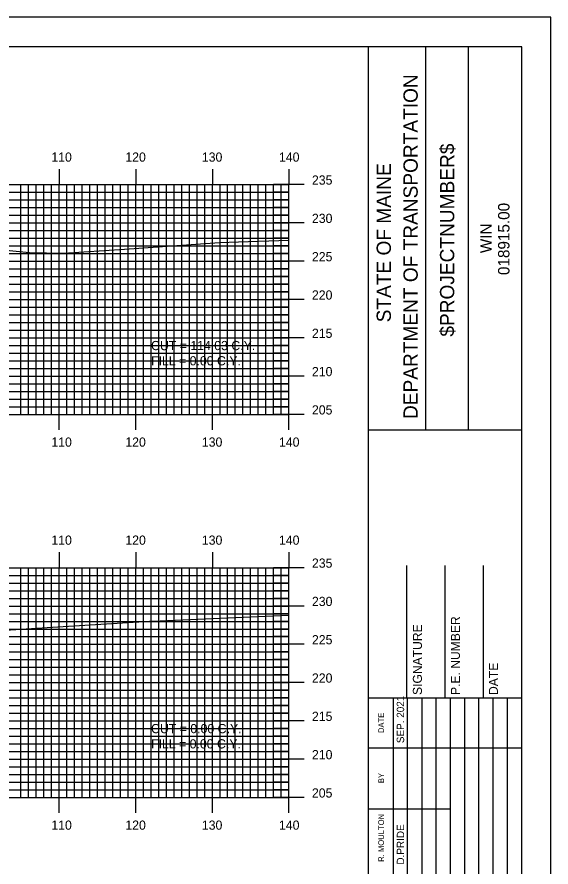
# Model space of a CAD drawing. Extents: x 850955 to 851298, y 364785 to 365005.
# Drawn here: x 851225.2 to 851294.9, y 364894.2 to 365005.1 of the extents above; entities that cross this region are included whole.
import ezdxf

# ---------------------------------------------------------------- set-up
doc = ezdxf.new("R2010")
doc.units = 0
for name, color, linetype in [('BORDER', 7, 'Continuous'), ('D_Text_Standard', 7, 'Continuous'), ('H_V ANNOTATION', 7, 'Continuous'), ('MAJOR', 7, 'Continuous'), ('MINOR', 7, 'Continuous'), ('PLOT BOUNDARY', 7, 'Continuous'), ('S_Roadway_Centerline', 7, 'Continuous')]:
    doc.layers.add(name, color=color, linetype=linetype)

msp = doc.modelspace()

# ---------------------------------------------------------------- linework, layer by layer
at = {"layer": 'BORDER'}
for p, q in [((851271.08, 364791.23), (851271.08, 365001.23)), ((851278.54, 364951.23), (851278.54, 365001.23)), ((851284.13, 364951.23), (851284.13, 365001.23)), ((851271.08, 364951.22), (851291.08, 364951.22)), ((851276.08, 364916.24), (851276.08, 364933.53)), ((851281.08, 364916.24), (851281.08, 364933.53)), ((851286.08, 364916.24), (851286.08, 364933.53)), ((851271.08, 364916.24), (851291.08, 364916.24))]:
    msp.add_line(p, q, dxfattribs=at)
msp.add_lwpolyline([(850971.08, 364791.23), (851291.08, 364791.23), (851291.08, 365001.23), (850971.08, 365001.23)], close=True, dxfattribs=at)
for points in [[(851274.31, 364909.74), (851274.31, 364916.24)], [(851276.17, 364881.24), (851276.17, 364916.24)], [(851278.04, 364916.24), (851278.04, 364881.24)], [(851279.9, 364881.24), (851279.9, 364916.24)], [(851281.76, 364881.24), (851281.76, 364916.24)], [(851283.63, 364881.24), (851283.63, 364916.24)], [(851285.49, 364881.24), (851285.49, 364916.24)], [(851287.35, 364881.24), (851287.35, 364916.24)], [(851289.22, 364881.24), (851289.22, 364916.24)], [(851274.31, 364881.24), (851274.31, 364914.83)], [(851271.08, 364909.74), (851291.08, 364909.74)], [(851271.08, 364901.74), (851274.31, 364901.74)], [(851274.31, 364901.74), (851281.76, 364901.74)]]:
    msp.add_lwpolyline(points, dxfattribs=at)
at = {"layer": 'MAJOR'}
for p, q in [((851230.68, 364985.24), (851230.68, 364983.23)), ((851240.68, 364985.24), (851240.68, 364983.23)), ((851250.68, 364985.24), (851250.68, 364983.23)), ((851260.68, 364985.24), (851260.68, 364983.23)), ((850980.68, 364983.23), (851260.68, 364983.23)), ((850980.68, 364983.23), (851260.68, 364983.23)), ((851230.68, 364953.23), (851230.68, 364983.23)), ((851240.68, 364953.23), (851240.68, 364983.23)), ((851250.68, 364953.23), (851250.68, 364983.23)), ((851262.68, 364983.23), (851258.67, 364983.23)), ((851260.68, 364953.23), (851260.68, 364983.23)), ((851260.68, 364953.23), (851260.68, 364983.23)), ((850980.68, 364978.23), (851260.68, 364978.23)), ((851262.68, 364978.23), (851258.67, 364978.23)), ((850980.68, 364973.23), (851260.68, 364973.23)), ((851262.68, 364973.23), (851258.67, 364973.23)), ((850980.68, 364968.23), (851260.68, 364968.23)), ((851262.68, 364968.23), (851258.67, 364968.23)), ((850980.68, 364963.23), (851260.68, 364963.23)), ((851262.68, 364963.23), (851258.67, 364963.23)), ((850980.68, 364958.23), (851260.68, 364958.23)), ((851262.68, 364958.23), (851258.67, 364958.23)), ((850980.68, 364953.23), (851260.68, 364953.23)), ((850980.68, 364953.23), (851260.68, 364953.23)), ((851230.68, 364951.23), (851230.68, 364953.23)), ((851240.68, 364951.23), (851240.68, 364953.23)), ((851250.68, 364951.23), (851250.68, 364953.23)), ((851262.68, 364953.23), (851258.67, 364953.23)), ((851260.68, 364951.23), (851260.68, 364953.23)), ((851230.68, 364935.24), (851230.68, 364933.23)), ((851240.68, 364935.24), (851240.68, 364933.23)), ((851250.68, 364935.24), (851250.68, 364933.23)), ((851260.68, 364935.24), (851260.68, 364933.23)), ((850980.68, 364933.23), (851260.68, 364933.23)), ((850980.68, 364933.23), (851260.68, 364933.23)), ((851230.68, 364903.23), (851230.68, 364933.23)), ((851240.68, 364903.23), (851240.68, 364933.23)), ((851250.68, 364903.23), (851250.68, 364933.23)), ((851262.68, 364933.23), (851258.67, 364933.23)), ((851260.68, 364903.23), (851260.68, 364933.23)), ((851260.68, 364903.23), (851260.68, 364933.23)), ((850980.68, 364928.23), (851260.68, 364928.23)), ((851262.68, 364928.23), (851258.67, 364928.23)), ((850980.68, 364923.23), (851260.68, 364923.23)), ((851262.68, 364923.23), (851258.67, 364923.23)), ((850980.68, 364918.23), (851260.68, 364918.23)), ((851262.68, 364918.23), (851258.67, 364918.23)), ((850980.68, 364913.23), (851260.68, 364913.23)), ((851262.68, 364913.23), (851258.67, 364913.23)), ((850980.68, 364908.23), (851260.68, 364908.23)), ((851262.68, 364908.23), (851258.67, 364908.23)), ((850980.68, 364903.23), (851260.68, 364903.23)), ((850980.68, 364903.23), (851260.68, 364903.23)), ((851230.68, 364901.23), (851230.68, 364903.23)), ((851240.68, 364901.23), (851240.68, 364903.23)), ((851250.68, 364901.23), (851250.68, 364903.23)), ((851262.68, 364903.23), (851258.67, 364903.23)), ((851260.68, 364901.23), (851260.68, 364903.23))]:
    msp.add_line(p, q, dxfattribs=at)
at = {"layer": 'MINOR'}
for p, q in [((851225.68, 364953.23), (851225.68, 364983.23)), ((851226.68, 364953.23), (851226.68, 364983.23)), ((851227.68, 364953.23), (851227.68, 364983.23)), ((851228.68, 364953.23), (851228.68, 364983.23)), ((851229.68, 364953.23), (851229.68, 364983.23)), ((851231.68, 364953.23), (851231.68, 364983.23)), ((851232.68, 364953.23), (851232.68, 364983.23)), ((851233.68, 364953.23), (851233.68, 364983.23)), ((851234.68, 364953.23), (851234.68, 364983.23)), ((851235.68, 364953.23), (851235.68, 364983.23)), ((851236.68, 364953.23), (851236.68, 364983.23)), ((851237.68, 364953.23), (851237.68, 364983.23)), ((851238.68, 364953.23), (851238.68, 364983.23)), ((851239.68, 364953.23), (851239.68, 364983.23)), ((851241.68, 364953.23), (851241.68, 364983.23)), ((851242.68, 364953.23), (851242.68, 364983.23)), ((851243.68, 364953.23), (851243.68, 364983.23)), ((851244.68, 364953.23), (851244.68, 364983.23)), ((851245.68, 364953.23), (851245.68, 364983.23)), ((851246.68, 364953.23), (851246.68, 364983.23)), ((851247.68, 364953.23), (851247.68, 364983.23)), ((851248.68, 364953.23), (851248.68, 364983.23)), ((851249.68, 364953.23), (851249.68, 364983.23)), ((851251.68, 364953.23), (851251.68, 364983.23)), ((851252.68, 364953.23), (851252.68, 364983.23)), ((851253.68, 364953.23), (851253.68, 364983.23)), ((851254.68, 364953.23), (851254.68, 364983.23)), ((851255.68, 364953.23), (851255.68, 364983.23)), ((851256.68, 364953.23), (851256.68, 364983.23)), ((851257.68, 364953.23), (851257.68, 364983.23)), ((851258.68, 364953.23), (851258.68, 364983.23)), ((851259.68, 364953.23), (851259.68, 364983.23)), ((850980.68, 364982.23), (851260.68, 364982.23)), ((851260.68, 364982.23), (851258.67, 364982.23)), ((850980.68, 364981.23), (851260.68, 364981.23)), ((851260.68, 364981.23), (851258.67, 364981.23)), ((850980.68, 364980.23), (851260.68, 364980.23)), ((851260.68, 364980.23), (851258.67, 364980.23)), ((850980.68, 364979.23), (851260.68, 364979.23)), ((851260.68, 364979.23), (851258.67, 364979.23)), ((850980.68, 364977.23), (851260.68, 364977.23)), ((851260.68, 364977.23), (851258.67, 364977.23)), ((850980.68, 364976.23), (851260.68, 364976.23)), ((851260.68, 364976.23), (851258.67, 364976.23)), ((850980.68, 364975.23), (851260.68, 364975.23)), ((851260.68, 364975.23), (851258.67, 364975.23)), ((850980.68, 364974.23), (851260.68, 364974.23)), ((851260.68, 364974.23), (851258.67, 364974.23)), ((850980.68, 364972.23), (851260.68, 364972.23)), ((851260.68, 364972.23), (851258.67, 364972.23)), ((850980.68, 364971.23), (851260.68, 364971.23)), ((851260.68, 364971.23), (851258.67, 364971.23)), ((850980.68, 364970.23), (851260.68, 364970.23)), ((851260.68, 364970.23), (851258.67, 364970.23)), ((850980.68, 364969.23), (851260.68, 364969.23)), ((851260.68, 364969.23), (851258.67, 364969.23)), ((850980.68, 364967.23), (851260.68, 364967.23)), ((851260.68, 364967.23), (851258.67, 364967.23)), ((850980.68, 364966.23), (851260.68, 364966.23)), ((851260.68, 364966.23), (851258.67, 364966.23)), ((850980.68, 364965.23), (851260.68, 364965.23)), ((851260.68, 364965.23), (851258.67, 364965.23)), ((850980.68, 364964.23), (851260.68, 364964.23)), ((851260.68, 364964.23), (851258.67, 364964.23)), ((850980.68, 364962.23), (851260.68, 364962.23)), ((851260.68, 364962.23), (851258.67, 364962.23)), ((850980.68, 364961.23), (851260.68, 364961.23)), ((851260.68, 364961.23), (851258.67, 364961.23)), ((850980.68, 364960.23), (851260.68, 364960.23)), ((851260.68, 364960.23), (851258.67, 364960.23)), ((850980.68, 364959.23), (851260.68, 364959.23)), ((851260.68, 364959.23), (851258.67, 364959.23)), ((850980.68, 364957.23), (851260.68, 364957.23)), ((850980.68, 364956.23), (851260.68, 364956.23)), ((851260.68, 364957.23), (851258.67, 364957.23)), ((851260.68, 364956.23), (851258.67, 364956.23)), ((850980.68, 364955.23), (851260.68, 364955.23)), ((851260.68, 364955.23), (851258.67, 364955.23)), ((850980.68, 364954.23), (851260.68, 364954.23)), ((851260.68, 364954.23), (851258.67, 364954.23)), ((851225.68, 364903.23), (851225.68, 364933.23)), ((851226.68, 364903.23), (851226.68, 364933.23)), ((851227.68, 364903.23), (851227.68, 364933.23)), ((851228.68, 364903.23), (851228.68, 364933.23)), ((851229.68, 364903.23), (851229.68, 364933.23)), ((851231.68, 364903.23), (851231.68, 364933.23)), ((851232.68, 364903.23), (851232.68, 364933.23)), ((851233.68, 364903.23), (851233.68, 364933.23)), ((851234.68, 364903.23), (851234.68, 364933.23)), ((851235.68, 364903.23), (851235.68, 364933.23)), ((851236.68, 364903.23), (851236.68, 364933.23)), ((851237.68, 364903.23), (851237.68, 364933.23)), ((851238.68, 364903.23), (851238.68, 364933.23)), ((851239.68, 364903.23), (851239.68, 364933.23)), ((851241.68, 364903.23), (851241.68, 364933.23)), ((851242.68, 364903.23), (851242.68, 364933.23)), ((851243.68, 364903.23), (851243.68, 364933.23)), ((851244.68, 364903.23), (851244.68, 364933.23)), ((851245.68, 364903.23), (851245.68, 364933.23)), ((851246.68, 364903.23), (851246.68, 364933.23)), ((851247.68, 364903.23), (851247.68, 364933.23)), ((851248.68, 364903.23), (851248.68, 364933.23)), ((851249.68, 364903.23), (851249.68, 364933.23)), ((851251.68, 364903.23), (851251.68, 364933.23)), ((851252.68, 364903.23), (851252.68, 364933.23)), ((851253.68, 364903.23), (851253.68, 364933.23)), ((851254.68, 364903.23), (851254.68, 364933.23)), ((851255.68, 364903.23), (851255.68, 364933.23)), ((851256.68, 364903.23), (851256.68, 364933.23)), ((851257.68, 364903.23), (851257.68, 364933.23)), ((851258.68, 364903.23), (851258.68, 364933.23)), ((851259.68, 364903.23), (851259.68, 364933.23)), ((850980.68, 364932.23), (851260.68, 364932.23)), ((851260.68, 364932.23), (851258.67, 364932.23)), ((850980.68, 364931.23), (851260.68, 364931.23)), ((851260.68, 364931.23), (851258.67, 364931.23)), ((850980.68, 364930.23), (851260.68, 364930.23)), ((851260.68, 364930.23), (851258.67, 364930.23)), ((850980.68, 364929.23), (851260.68, 364929.23)), ((851260.68, 364929.23), (851258.67, 364929.23)), ((850980.68, 364927.23), (851260.68, 364927.23)), ((850980.68, 364926.23), (851260.68, 364926.23)), ((851260.68, 364927.23), (851258.67, 364927.23)), ((851260.68, 364926.23), (851258.67, 364926.23)), ((850980.68, 364925.23), (851260.68, 364925.23)), ((851260.68, 364925.23), (851258.67, 364925.23)), ((850980.68, 364924.23), (851260.68, 364924.23)), ((851260.68, 364924.23), (851258.67, 364924.23)), ((850980.68, 364922.23), (851260.68, 364922.23)), ((851260.68, 364922.23), (851258.67, 364922.23)), ((850980.68, 364921.23), (851260.68, 364921.23)), ((851260.68, 364921.23), (851258.67, 364921.23)), ((850980.68, 364920.23), (851260.68, 364920.23)), ((851260.68, 364920.23), (851258.67, 364920.23)), ((850980.68, 364919.23), (851260.68, 364919.23)), ((851260.68, 364919.23), (851258.67, 364919.23)), ((850980.68, 364917.23), (851260.68, 364917.23)), ((850980.68, 364916.23), (851260.68, 364916.23)), ((851260.68, 364917.23), (851258.67, 364917.23)), ((851260.68, 364916.23), (851258.67, 364916.23)), ((850980.68, 364915.23), (851260.68, 364915.23)), ((851260.68, 364915.23), (851258.67, 364915.23)), ((850980.68, 364914.23), (851260.68, 364914.23)), ((851260.68, 364914.23), (851258.67, 364914.23)), ((850980.68, 364912.23), (851260.68, 364912.23)), ((851260.68, 364912.23), (851258.67, 364912.23)), ((850980.68, 364911.23), (851260.68, 364911.23)), ((851260.68, 364911.23), (851258.67, 364911.23)), ((850980.68, 364910.23), (851260.68, 364910.23)), ((851260.68, 364910.23), (851258.67, 364910.23)), ((850980.68, 364909.23), (851260.68, 364909.23)), ((851260.68, 364909.23), (851258.67, 364909.23)), ((850980.68, 364907.23), (851260.68, 364907.23)), ((850980.68, 364906.23), (851260.68, 364906.23)), ((851260.68, 364907.23), (851258.67, 364907.23)), ((851260.68, 364906.23), (851258.67, 364906.23)), ((850980.68, 364905.23), (851260.68, 364905.23)), ((851260.68, 364905.23), (851258.67, 364905.23)), ((850980.68, 364904.23), (851260.68, 364904.23)), ((851260.68, 364904.23), (851258.67, 364904.23))]:
    msp.add_line(p, q, dxfattribs=at)
at = {"layer": 'PLOT BOUNDARY'}
msp.add_lwpolyline([(850954.89, 364785.11), (851294.89, 364785.11), (851294.89, 365005.11), (850954.89, 365005.11)], close=True, dxfattribs=at)
at = {"layer": 'S_Roadway_Centerline'}
for points in [[(851153.68, 364963.83), (851154.62, 364963.82), (851155.41, 364964.25), (851155.97, 364964.61), (851156.95, 364964.91), (851158.17, 364965.68), (851163.84, 364968.62), (851166.74, 364969.22), (851173.34, 364970.67), (851175.2, 364970.95), (851177.07, 364971.37), (851182.91, 364972.37), (851193.98, 364974.3), (851202.96, 364975.31), (851213.53, 364975.62), (851218.51, 364975.18), (851226.8, 364974.39), (851231.26, 364974.28), (851239.23, 364974.83), (851250.39, 364975.59), (851251.62, 364975.67), (851254.1, 364975.76), (851260.68, 364975.99)], [(851152.46, 364915.63), (851155.29, 364915.9), (851155.29, 364915.9), (851155.31, 364915.91), (851164.03, 364919.93), (851166.94, 364920.87), (851169.21, 364921.52), (851173.19, 364922.06), (851174.3, 364922.37), (851181.74, 364923.35), (851186.88, 364924.29), (851193.89, 364924.62), (851206.34, 364925.09), (851206.58, 364925.12), (851207.05, 364925.12), (851218.3, 364924.83), (851223.64, 364925.06), (851230.51, 364925.5), (851242.47, 364926.24), (851242.6, 364926.24), (851242.85, 364926.25), (851260.68, 364927.04)]]:
    msp.add_lwpolyline(points, dxfattribs=at)

# ---------------------------------------------------------------- texts
at = {"layer": 'BORDER'}
for s, height, p in [('DEPARTMENT OF TRANSPORTATION', 1.8635, (851277.49, 364952.64)), ('$PROJECTNUMBER$', 1.8635, (851282.26, 364963.39)), ('STATE OF MAINE', 1.8635, (851273.99, 364965.26)), ('018915.00', 1.491, (851289.47, 364971.43)), ('WIN', 1.491, (851287.15, 364974.29)), ('P.E. NUMBER', 1.1811, (851283, 364916.62)), ('SIGNATURE', 1.181, (851278.04, 364916.62)), ('DATE', 1.181, (851287.96, 364916.62)), ('SEP. 2021', 0.969, (851275.72, 364910.33)), ('DATE', 0.743, (851273.09, 364911.65)), ('BY', 0.743, (851273.09, 364905.11)), ('R. MOULTON', 0.745, (851273.09, 364894.84)), ('D.PRIDE', 0.969, (851275.72, 364894.48))]:
    msp.add_text(s, height=height, rotation=90, dxfattribs=at).set_placement(p)
at = {"layer": 'D_Text_Standard'}
for s, p in [('CUT = 114.03 C.Y.', (851242.68, 364961.63)), ('FILL = 0.00 C.Y.', (851242.68, 364959.64)), ('CUT = 0.00 C.Y.', (851242.68, 364911.63)), ('FILL = 0.00 C.Y.', (851242.68, 364909.64))]:
    msp.add_text(s, height=1.2, dxfattribs=at).set_placement(p)
at = {"layer": 'H_V ANNOTATION'}
for s, p in [('110', (851229.66, 364986.23)), ('120', (851239.32, 364986.23)), ('130', (851249.31, 364986.23)), ('140', (851259.38, 364986.23)), ('235', (851263.68, 364983.23)), ('230', (851263.68, 364978.23)), ('225', (851263.68, 364973.23)), ('220', (851263.68, 364968.23)), ('215', (851263.68, 364963.23)), ('210', (851263.68, 364958.23)), ('205', (851263.68, 364953.23)), ('110', (851229.66, 364949.03)), ('120', (851239.32, 364949.03)), ('130', (851249.31, 364949.03)), ('140', (851259.38, 364949.03)), ('110', (851229.66, 364936.23)), ('120', (851239.32, 364936.23)), ('130', (851249.31, 364936.23)), ('140', (851259.38, 364936.23)), ('235', (851263.68, 364933.23)), ('230', (851263.68, 364928.23)), ('225', (851263.68, 364923.23)), ('220', (851263.68, 364918.23)), ('215', (851263.68, 364913.23)), ('210', (851263.68, 364908.23)), ('205', (851263.68, 364903.23)), ('110', (851229.66, 364899.03)), ('120', (851239.32, 364899.03)), ('130', (851249.31, 364899.03)), ('140', (851259.38, 364899.03))]:
    msp.add_text(s, height=1.2, dxfattribs=at).set_placement(p)

doc.saveas('drawing.dxf')
